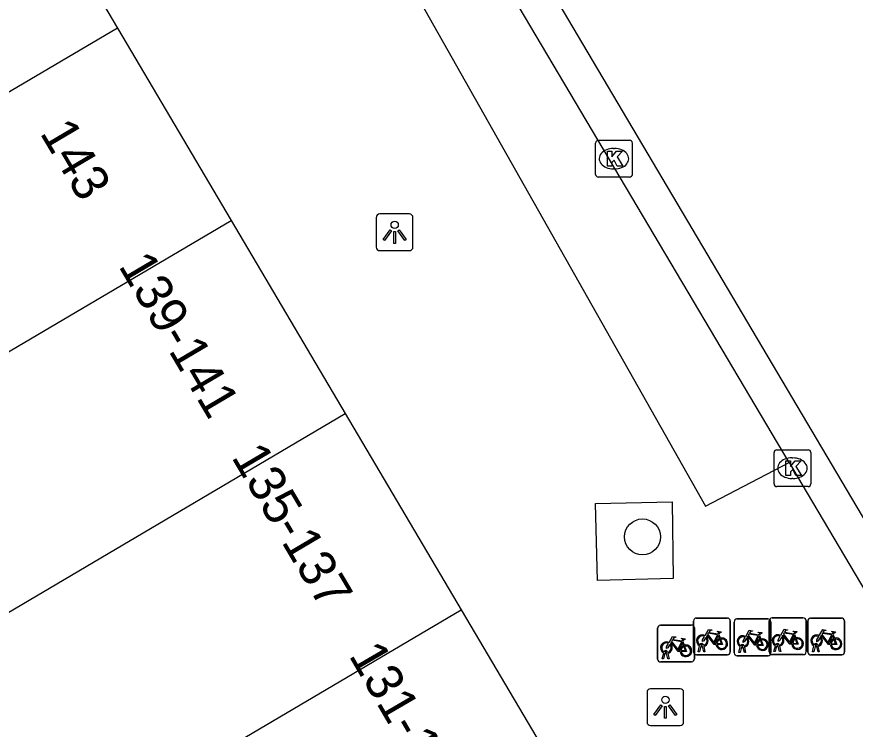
# Model space of a CAD drawing. Extents: x 160379 to 161131, y 383940 to 384849.
# Drawn here: x 161035.54 to 161058.35, y 384440.01 to 384459.39 of the extents above; entities that cross this region are included whole.
import ezdxf

# ---------------------------------------------------------------- set-up
doc = ezdxf.new("R2010")
doc.units = 0
for name, color, linetype in [('IMGEO_Boom', 7, 'Continuous'), ('IMGEO_Fietsenrek', 7, 'Continuous'), ('IMGEO_Fietspad_gesloten', 7, 'Continuous'), ('IMGEO_Fietspad_open', 7, 'Continuous'), ('IMGEO_Kolk', 7, 'Continuous'), ('IMGEO_Lichtpunt', 7, 'Continuous'), ('IMGEO_Pand', 7, 'Continuous'), ('IMGEO_Pand_nummerreeks', 7, 'Continuous'), ('IMGEO_Voetpad_open', 7, 'Continuous')]:
    doc.layers.add(name, color=color, linetype=linetype)

msp = doc.modelspace()

# ---------------------------------------------------------------- linework, layer by layer
at = {"layer": 'IMGEO_Boom'}
msp.add_circle((161052.564, 384445.239), 0.489, dxfattribs=at)
at = {"layer": 'IMGEO_Fietsenrek'}
for p, q in [((161054.027, 384443.033), (161054.868, 384443.033)), ((161054.868, 384443.033), (161054.027, 384443.033)), ((161055.133, 384443.009), (161055.974, 384443.009)), ((161055.974, 384443.009), (161055.133, 384443.009)), ((161056.089, 384443.037), (161056.93, 384443.037)), ((161056.93, 384443.037), (161056.089, 384443.037)), ((161057.136, 384443.031), (161057.977, 384443.031)), ((161057.977, 384443.031), (161057.136, 384443.031)), ((161053.05, 384442.842), (161053.891, 384442.842)), ((161053.891, 384442.842), (161053.05, 384442.842)), ((161053.952, 384442.108), (161053.952, 384442.949)), ((161053.952, 384442.949), (161053.952, 384442.108)), ((161054.952, 384442.958), (161054.952, 384442.117)), ((161054.952, 384442.117), (161054.952, 384442.958)), ((161055.058, 384442.084), (161055.058, 384442.925)), ((161055.058, 384442.925), (161055.058, 384442.084)), ((161056.014, 384442.112), (161056.014, 384442.953)), ((161056.014, 384442.953), (161056.014, 384442.112)), ((161056.058, 384442.934), (161056.058, 384442.093)), ((161056.058, 384442.093), (161056.058, 384442.934)), ((161057.014, 384442.962), (161057.014, 384442.121)), ((161057.014, 384442.121), (161057.014, 384442.962)), ((161057.061, 384442.106), (161057.061, 384442.947)), ((161057.061, 384442.947), (161057.061, 384442.106)), ((161058.061, 384442.956), (161058.061, 384442.115)), ((161058.061, 384442.115), (161058.061, 384442.956)), ((161052.975, 384441.917), (161052.975, 384442.758)), ((161052.975, 384442.758), (161052.975, 384441.917)), ((161053.975, 384442.767), (161053.975, 384441.926)), ((161053.975, 384441.926), (161053.975, 384442.767)), ((161054.639, 384442.582), (161054.675, 384442.487)), ((161055.745, 384442.558), (161055.781, 384442.463)), ((161056.701, 384442.586), (161056.737, 384442.491)), ((161057.748, 384442.58), (161057.784, 384442.485)), ((161053.662, 384442.391), (161053.698, 384442.296)), ((161053.213, 384442.098), (161053.212, 384442.102)), ((161053.244, 384442.109), (161053.245, 384442.102)), ((161054.079, 384442.117), (161054.118, 384442.277)), ((161054.113, 384442.117), (161054.079, 384442.117)), ((161054.148, 384442.265), (161054.113, 384442.117)), ((161054.19, 384442.289), (161054.189, 384442.293)), ((161054.231, 384442.117), (161054.197, 384442.259)), ((161054.221, 384442.3), (161054.222, 384442.293)), ((161054.229, 384442.263), (161054.264, 384442.117)), ((161054.264, 384442.117), (161054.231, 384442.117)), ((161055.185, 384442.093), (161055.224, 384442.253)), ((161055.219, 384442.093), (161055.185, 384442.093)), ((161055.254, 384442.241), (161055.219, 384442.093)), ((161055.296, 384442.265), (161055.295, 384442.269)), ((161055.337, 384442.093), (161055.303, 384442.235)), ((161055.327, 384442.276), (161055.328, 384442.269)), ((161055.335, 384442.239), (161055.37, 384442.093)), ((161055.37, 384442.093), (161055.337, 384442.093)), ((161056.141, 384442.121), (161056.18, 384442.281)), ((161056.175, 384442.121), (161056.141, 384442.121)), ((161056.21, 384442.269), (161056.175, 384442.121)), ((161056.252, 384442.293), (161056.251, 384442.297)), ((161056.293, 384442.121), (161056.259, 384442.263)), ((161056.283, 384442.304), (161056.284, 384442.297)), ((161056.291, 384442.267), (161056.326, 384442.121)), ((161056.326, 384442.121), (161056.293, 384442.121)), ((161057.188, 384442.115), (161057.227, 384442.275)), ((161057.222, 384442.115), (161057.188, 384442.115)), ((161057.257, 384442.263), (161057.222, 384442.115)), ((161057.299, 384442.287), (161057.298, 384442.291)), ((161057.34, 384442.115), (161057.306, 384442.257)), ((161057.33, 384442.298), (161057.331, 384442.291)), ((161057.338, 384442.261), (161057.373, 384442.115)), ((161057.373, 384442.115), (161057.34, 384442.115)), ((161053.102, 384441.926), (161053.141, 384442.086)), ((161053.136, 384441.926), (161053.102, 384441.926)), ((161053.171, 384442.074), (161053.136, 384441.926)), ((161053.254, 384441.926), (161053.22, 384442.068)), ((161053.252, 384442.072), (161053.287, 384441.926)), ((161053.287, 384441.926), (161053.254, 384441.926)), ((161054.877, 384442.033), (161054.036, 384442.033)), ((161054.036, 384442.033), (161054.877, 384442.033)), ((161055.983, 384442.009), (161055.142, 384442.009)), ((161055.142, 384442.009), (161055.983, 384442.009)), ((161056.939, 384442.037), (161056.098, 384442.037)), ((161056.098, 384442.037), (161056.939, 384442.037)), ((161057.986, 384442.031), (161057.145, 384442.031)), ((161057.145, 384442.031), (161057.986, 384442.031)), ((161053.9, 384441.842), (161053.059, 384441.842)), ((161053.059, 384441.842), (161053.9, 384441.842))]:
    msp.add_line(p, q, dxfattribs=at)
for points in [[(161054.265, 384442.559), (161054.36, 384442.723), (161054.446, 384442.709), (161054.448, 384442.7), (161054.392, 384442.689), (161054.365, 384442.644), (161054.621, 384442.603)], [(161054.561, 384442.315), (161054.511, 384442.315), (161054.32, 384442.566), (161054.301, 384442.534)], [(161054.608, 384442.578), (161054.351, 384442.619), (161054.334, 384442.59), (161054.501, 384442.37), (161054.608, 384442.578)], [(161054.656, 384442.48), (161054.626, 384442.557), (161054.517, 384442.339), (161054.56, 384442.339)], [(161054.621, 384442.603), (161054.646, 384442.652), (161054.64, 384442.656), (161054.617, 384442.66), (161054.605, 384442.667), (161054.604, 384442.67), (161054.606, 384442.675), (161054.701, 384442.66), (161054.703, 384442.65), (161054.693, 384442.637), (161054.681, 384442.631), (161054.667, 384442.637), (161054.639, 384442.582)], [(161055.371, 384442.535), (161055.466, 384442.699), (161055.552, 384442.685), (161055.554, 384442.676), (161055.498, 384442.665), (161055.471, 384442.62), (161055.727, 384442.579)], [(161055.714, 384442.554), (161055.457, 384442.595), (161055.44, 384442.566), (161055.607, 384442.346), (161055.714, 384442.554)], [(161055.727, 384442.579), (161055.752, 384442.628), (161055.746, 384442.632), (161055.723, 384442.636), (161055.711, 384442.643), (161055.71, 384442.646), (161055.712, 384442.651), (161055.807, 384442.636), (161055.809, 384442.626), (161055.799, 384442.613), (161055.787, 384442.607), (161055.773, 384442.613), (161055.745, 384442.558)], [(161056.327, 384442.563), (161056.422, 384442.727), (161056.508, 384442.713), (161056.51, 384442.704), (161056.454, 384442.693), (161056.427, 384442.648), (161056.683, 384442.607)], [(161056.623, 384442.319), (161056.573, 384442.319), (161056.382, 384442.57), (161056.363, 384442.538)], [(161056.67, 384442.582), (161056.413, 384442.623), (161056.396, 384442.594), (161056.563, 384442.374), (161056.67, 384442.582)], [(161056.718, 384442.484), (161056.688, 384442.561), (161056.579, 384442.343), (161056.622, 384442.343)], [(161056.683, 384442.607), (161056.708, 384442.656), (161056.702, 384442.66), (161056.679, 384442.664), (161056.667, 384442.671), (161056.666, 384442.674), (161056.668, 384442.679), (161056.763, 384442.664), (161056.765, 384442.654), (161056.755, 384442.641), (161056.743, 384442.635), (161056.729, 384442.641), (161056.701, 384442.586)], [(161057.374, 384442.557), (161057.469, 384442.721), (161057.555, 384442.707), (161057.557, 384442.698), (161057.501, 384442.687), (161057.474, 384442.642), (161057.73, 384442.601)], [(161057.67, 384442.313), (161057.62, 384442.313), (161057.429, 384442.564), (161057.41, 384442.532)], [(161057.717, 384442.576), (161057.46, 384442.617), (161057.443, 384442.588), (161057.61, 384442.368), (161057.717, 384442.576)], [(161057.765, 384442.478), (161057.735, 384442.555), (161057.626, 384442.337), (161057.669, 384442.337)], [(161057.73, 384442.601), (161057.755, 384442.65), (161057.749, 384442.654), (161057.726, 384442.658), (161057.714, 384442.665), (161057.713, 384442.668), (161057.715, 384442.673), (161057.81, 384442.658), (161057.812, 384442.648), (161057.802, 384442.635), (161057.79, 384442.629), (161057.776, 384442.635), (161057.748, 384442.58)], [(161053.309, 384442.316), (161053.257, 384442.226), (161053.217, 384442.201), (161053.218, 384442.248), (161053.273, 384442.342)], [(161053.288, 384442.368), (161053.383, 384442.532), (161053.469, 384442.518), (161053.471, 384442.509), (161053.415, 384442.498), (161053.388, 384442.453), (161053.644, 384442.412)], [(161053.584, 384442.124), (161053.534, 384442.124), (161053.343, 384442.375), (161053.324, 384442.343)], [(161053.631, 384442.387), (161053.374, 384442.428), (161053.357, 384442.399), (161053.524, 384442.179), (161053.631, 384442.387)], [(161053.679, 384442.289), (161053.649, 384442.366), (161053.54, 384442.148), (161053.583, 384442.148)], [(161053.644, 384442.412), (161053.669, 384442.461), (161053.663, 384442.465), (161053.64, 384442.469), (161053.628, 384442.476), (161053.627, 384442.479), (161053.629, 384442.484), (161053.724, 384442.469), (161053.726, 384442.459), (161053.716, 384442.446), (161053.704, 384442.44), (161053.69, 384442.446), (161053.662, 384442.391)], [(161054.286, 384442.507), (161054.234, 384442.417), (161054.194, 384442.392), (161054.195, 384442.439), (161054.25, 384442.533)], [(161054.59, 384442.339), (161054.71, 384442.338), (161054.666, 384442.452)], [(161054.686, 384442.459), (161054.741, 384442.314), (161054.591, 384442.314)], [(161055.392, 384442.483), (161055.34, 384442.393), (161055.3, 384442.368), (161055.301, 384442.415), (161055.356, 384442.509)], [(161055.667, 384442.291), (161055.617, 384442.291), (161055.426, 384442.542), (161055.407, 384442.51)], [(161055.762, 384442.456), (161055.732, 384442.533), (161055.623, 384442.315), (161055.666, 384442.315)], [(161055.696, 384442.315), (161055.816, 384442.314), (161055.772, 384442.428)], [(161055.792, 384442.435), (161055.847, 384442.29), (161055.697, 384442.29)], [(161056.348, 384442.511), (161056.296, 384442.421), (161056.256, 384442.396), (161056.257, 384442.443), (161056.312, 384442.537)], [(161056.652, 384442.343), (161056.772, 384442.342), (161056.728, 384442.456)], [(161056.748, 384442.463), (161056.803, 384442.318), (161056.653, 384442.318)], [(161057.395, 384442.505), (161057.343, 384442.415), (161057.303, 384442.39), (161057.304, 384442.437), (161057.359, 384442.531)], [(161057.699, 384442.337), (161057.819, 384442.336), (161057.775, 384442.45)], [(161057.795, 384442.457), (161057.85, 384442.312), (161057.7, 384442.312)], [(161053.613, 384442.148), (161053.733, 384442.147), (161053.689, 384442.261)], [(161053.709, 384442.268), (161053.764, 384442.123), (161053.614, 384442.123)]]:
    msp.add_lwpolyline(points, dxfattribs=at)
for centre, radius, start, end in [((161054.03, 384442.955), 0.0779, 92.4484, 184.2845), ((161054.03, 384442.955), 0.0779, 92.4484, 184.2845), ((161054.874, 384442.955), 0.0779, 2.4484, 94.2845), ((161054.874, 384442.955), 0.0779, 2.4484, 94.2845), ((161055.136, 384442.931), 0.0779, 92.4484, 184.2845), ((161055.136, 384442.931), 0.0779, 92.4484, 184.2845), ((161055.98, 384442.931), 0.0779, 2.4484, 94.2845), ((161055.98, 384442.931), 0.0779, 2.4484, 94.2845), ((161056.092, 384442.959), 0.0779, 92.4484, 184.2845), ((161056.092, 384442.959), 0.0779, 92.4484, 184.2845), ((161056.936, 384442.959), 0.0779, 2.4484, 94.2845), ((161056.936, 384442.959), 0.0779, 2.4484, 94.2845), ((161057.139, 384442.953), 0.0779, 92.4484, 184.2845), ((161057.139, 384442.953), 0.0779, 92.4484, 184.2845), ((161057.983, 384442.953), 0.0779, 2.4484, 94.2845), ((161057.983, 384442.953), 0.0779, 2.4484, 94.2845), ((161053.053, 384442.764), 0.0779, 92.4484, 184.2845), ((161053.053, 384442.764), 0.0779, 92.4484, 184.2845), ((161053.897, 384442.764), 0.0779, 2.4484, 94.2845), ((161053.897, 384442.764), 0.0779, 2.4484, 94.2845), ((161054.192, 384442.418), 0.159, 62.6766, 242.1369), ((161054.192, 384442.418), 0.129, 63.3192, 238.903), ((161055.298, 384442.394), 0.159, 62.6766, 242.1369), ((161056.254, 384442.422), 0.159, 62.6766, 242.1369), ((161056.254, 384442.422), 0.129, 63.3192, 238.903), ((161057.301, 384442.416), 0.159, 62.6766, 242.1369), ((161057.301, 384442.416), 0.129, 63.3192, 238.903), ((161053.215, 384442.227), 0.159, 62.6766, 242.1369), ((161053.215, 384442.227), 0.129, 63.3192, 238.903), ((161053.215, 384442.227), 0.159, 283.5766, 46.6042), ((161054.172, 384442.289), 0.0499, 12.8025, 158.6934), ((161054.192, 384442.418), 0.129, 283.6043, 43.4302), ((161054.192, 384442.418), 0.159, 283.5766, 46.6042), ((161054.719, 384442.334), 0.159, 113.3408, 178.3217), ((161054.719, 384442.334), 0.159, 187.0065, 105.7708), ((161054.719, 384442.334), 0.129, 113.923, 177.9556), ((161054.719, 384442.334), 0.129, 188.6715, 104.5883), ((161055.298, 384442.394), 0.129, 63.3192, 238.903), ((161055.298, 384442.394), 0.129, 283.6043, 43.4302), ((161055.298, 384442.394), 0.159, 283.5766, 46.6042), ((161055.825, 384442.31), 0.159, 113.3408, 178.3217), ((161055.825, 384442.31), 0.159, 187.0065, 105.7708), ((161055.825, 384442.31), 0.129, 113.923, 177.9556), ((161055.825, 384442.31), 0.129, 188.6715, 104.5883), ((161056.234, 384442.293), 0.0499, 12.8025, 158.6934), ((161056.254, 384442.422), 0.129, 283.6043, 43.4302), ((161056.254, 384442.422), 0.159, 283.5766, 46.6042), ((161056.781, 384442.338), 0.159, 113.3408, 178.3217), ((161056.781, 384442.338), 0.159, 187.0065, 105.7708), ((161056.781, 384442.338), 0.129, 113.923, 177.9556), ((161056.781, 384442.338), 0.129, 188.6715, 104.5883), ((161057.281, 384442.287), 0.0499, 12.8025, 158.6934), ((161057.301, 384442.416), 0.129, 283.6043, 43.4302), ((161057.301, 384442.416), 0.159, 283.5766, 46.6042), ((161057.828, 384442.332), 0.159, 113.3408, 178.3217), ((161057.828, 384442.332), 0.159, 187.0065, 105.7708), ((161057.828, 384442.332), 0.129, 113.923, 177.9556), ((161057.828, 384442.332), 0.129, 188.6715, 104.5883), ((161053.195, 384442.098), 0.0499, 12.8025, 158.6934), ((161053.195, 384442.098), 0.0174, 12.8025, 163.4502), ((161053.215, 384442.227), 0.129, 253.415, 269.0204), ((161053.215, 384442.227), 0.129, 283.6043, 43.4302), ((161053.742, 384442.143), 0.159, 113.3408, 178.3217), ((161053.742, 384442.143), 0.159, 187.0065, 105.7708), ((161053.742, 384442.143), 0.129, 113.923, 177.9556), ((161053.742, 384442.143), 0.129, 188.6715, 104.5883), ((161054.03, 384442.111), 0.0779, 182.4484, 274.2845), ((161054.03, 384442.111), 0.0779, 182.4484, 274.2845), ((161054.192, 384442.418), 0.159, 253.9967, 271.7867), ((161054.172, 384442.289), 0.0174, 12.8025, 163.4502), ((161054.192, 384442.418), 0.129, 253.415, 269.0204), ((161054.874, 384442.111), 0.0779, 272.4484, 4.2845), ((161054.874, 384442.111), 0.0779, 272.4484, 4.2845), ((161055.278, 384442.265), 0.0499, 12.8025, 158.6934), ((161055.298, 384442.394), 0.159, 253.9967, 271.7867), ((161055.278, 384442.265), 0.0174, 12.8025, 163.4502), ((161055.298, 384442.394), 0.129, 253.415, 269.0204), ((161055.98, 384442.087), 0.0779, 272.4484, 4.2845), ((161055.98, 384442.087), 0.0779, 272.4484, 4.2845), ((161056.092, 384442.115), 0.0779, 182.4484, 274.2845), ((161056.092, 384442.115), 0.0779, 182.4484, 274.2845), ((161056.254, 384442.422), 0.159, 253.9967, 271.7867), ((161056.234, 384442.293), 0.0174, 12.8025, 163.4502), ((161056.254, 384442.422), 0.129, 253.415, 269.0204), ((161056.936, 384442.115), 0.0779, 272.4484, 4.2845), ((161056.936, 384442.115), 0.0779, 272.4484, 4.2845), ((161057.139, 384442.109), 0.0779, 182.4484, 274.2845), ((161057.139, 384442.109), 0.0779, 182.4484, 274.2845), ((161057.301, 384442.416), 0.159, 253.9967, 271.7867), ((161057.281, 384442.287), 0.0174, 12.8025, 163.4502), ((161057.301, 384442.416), 0.129, 253.415, 269.0204), ((161057.983, 384442.109), 0.0779, 272.4484, 4.2845), ((161057.983, 384442.109), 0.0779, 272.4484, 4.2845), ((161053.053, 384441.92), 0.0779, 182.4484, 274.2845), ((161053.053, 384441.92), 0.0779, 182.4484, 274.2845), ((161053.215, 384442.227), 0.159, 253.9967, 271.7867), ((161053.897, 384441.92), 0.0779, 272.4484, 4.2845), ((161053.897, 384441.92), 0.0779, 272.4484, 4.2845), ((161055.136, 384442.087), 0.0779, 182.4484, 274.2845), ((161055.136, 384442.087), 0.0779, 182.4484, 274.2845)]:
    msp.add_arc(centre, radius, start, end, dxfattribs=at)
at = {"layer": 'IMGEO_Fietspad_gesloten'}
msp.add_lwpolyline([(161035.767, 384484.262), (161059.475, 384444.228)], dxfattribs=at)
at = {"layer": 'IMGEO_Fietspad_open'}
for points in [[(161056.553, 384447.261), (161047.068, 384463.264), (161045.415, 384466.054), (161044.226, 384468.061)], [(161056.553, 384447.261), (161056.903, 384446.671), (161058.642, 384443.737)]]:
    msp.add_lwpolyline(points, dxfattribs=at)
at = {"layer": 'IMGEO_Kolk'}
for p, q in [((161051.361, 384456.028), (161052.213, 384456.028)), ((161051.286, 384455.102), (161051.286, 384455.954)), ((161051.774, 384455.808), (161051.799, 384455.808)), ((161052.287, 384455.954), (161052.287, 384455.102)), ((161051.797, 384455.248), (161051.772, 384455.248)), ((161052.213, 384455.028), (161051.361, 384455.028)), ((161056.217, 384447.609), (161057.069, 384447.609)), ((161056.142, 384446.683), (161056.142, 384447.535)), ((161056.63, 384447.389), (161056.655, 384447.389)), ((161057.143, 384447.535), (161057.143, 384446.683)), ((161056.653, 384446.829), (161056.628, 384446.829)), ((161057.069, 384446.609), (161056.217, 384446.609))]:
    msp.add_line(p, q, dxfattribs=at)
for points in [[(161051.361, 384456.028), (161052.213, 384456.028)], [(161051.286, 384455.102), (161051.286, 384455.954)], [(161052.287, 384455.954), (161052.287, 384455.102)], [(161051.607, 384455.728), (161051.73, 384455.728), (161051.73, 384455.577), (161051.86, 384455.728), (161052.024, 384455.728), (161051.878, 384455.577), (161052.031, 384455.328), (161051.879, 384455.328), (161051.794, 384455.492), (161051.73, 384455.425), (161051.73, 384455.328), (161051.607, 384455.328), (161051.607, 384455.728)], [(161052.213, 384455.028), (161051.361, 384455.028)], [(161056.217, 384447.609), (161057.069, 384447.609)], [(161056.142, 384446.683), (161056.142, 384447.535)], [(161057.143, 384447.535), (161057.143, 384446.683)], [(161056.463, 384447.309), (161056.586, 384447.309), (161056.586, 384447.158), (161056.716, 384447.309), (161056.88, 384447.309), (161056.734, 384447.158), (161056.887, 384446.909), (161056.735, 384446.909), (161056.65, 384447.073), (161056.586, 384447.006), (161056.586, 384446.909), (161056.463, 384446.909), (161056.463, 384447.309)], [(161057.069, 384446.609), (161056.217, 384446.609)]]:
    msp.add_lwpolyline(points, dxfattribs=at)
for centre, start, end in [((161051.363, 384455.952), 91.552, 178.448), ((161051.363, 384455.952), 91.552, 178.448), ((161052.211, 384455.952), 1.552, 88.448), ((161052.211, 384455.952), 1.552, 88.448), ((161051.363, 384455.104), 181.552, 268.448), ((161051.363, 384455.104), 181.552, 268.448), ((161052.211, 384455.104), 271.552, 358.448), ((161052.211, 384455.104), 271.552, 358.448), ((161056.219, 384447.533), 91.552, 178.448), ((161056.219, 384447.533), 91.552, 178.448), ((161057.067, 384447.533), 1.552, 88.448), ((161057.067, 384447.533), 1.552, 88.448), ((161056.219, 384446.685), 181.552, 268.448), ((161056.219, 384446.685), 181.552, 268.448), ((161057.067, 384446.685), 271.552, 358.448), ((161057.067, 384446.685), 271.552, 358.448)]:
    msp.add_arc(centre, 0.0765, start, end, dxfattribs=at)
for centre, major_axis, ratio, start_param, end_param in [((161051.773, 384455.528), (-0.387, 0.002), 0.722429, 4.712389, 7.853982), ((161051.798, 384455.528), (-0.39, 0.002), 0.717154, 1.570796, 4.712389), ((161056.629, 384447.109), (-0.387, 0.002), 0.722429, 4.712389, 7.853982), ((161056.654, 384447.109), (-0.39, 0.002), 0.717154, 1.570796, 4.712389)]:
    msp.add_ellipse(centre, major_axis=major_axis, ratio=ratio, start_param=start_param, end_param=end_param, dxfattribs=at)
at = {"layer": 'IMGEO_Lichtpunt'}
for p, q in [((161046.224, 384454.024), (161045.416, 384454.024)), ((161046.224, 384454.024), (161045.416, 384454.024)), ((161045.322, 384453.929), (161045.322, 384453.122)), ((161045.322, 384453.929), (161045.322, 384453.122)), ((161046.318, 384453.122), (161046.318, 384453.929)), ((161046.318, 384453.122), (161046.318, 384453.929)), ((161045.416, 384453.028), (161046.224, 384453.028)), ((161045.416, 384453.028), (161046.224, 384453.028)), ((161052.687, 384441.012), (161052.687, 384440.205)), ((161052.687, 384441.012), (161052.687, 384440.205)), ((161053.589, 384441.107), (161052.781, 384441.107)), ((161053.589, 384441.107), (161052.781, 384441.107)), ((161053.683, 384440.205), (161053.683, 384441.012)), ((161053.683, 384440.205), (161053.683, 384441.012)), ((161052.781, 384440.111), (161053.589, 384440.111)), ((161052.781, 384440.111), (161053.589, 384440.111))]:
    msp.add_line(p, q, dxfattribs=at)
for points in [[(161045.696, 384453.593), (161045.735, 384453.565), (161045.547, 384453.303), (161045.509, 384453.33), (161045.696, 384453.593)], [(161045.798, 384453.545), (161045.845, 384453.545), (161045.845, 384453.223), (161045.798, 384453.223), (161045.798, 384453.545)], [(161045.908, 384453.565), (161045.946, 384453.592), (161046.133, 384453.33), (161046.094, 384453.302), (161045.908, 384453.565)], [(161053.061, 384440.676), (161053.1, 384440.648), (161052.912, 384440.386), (161052.874, 384440.413), (161053.061, 384440.676)], [(161053.163, 384440.628), (161053.21, 384440.628), (161053.21, 384440.306), (161053.163, 384440.306), (161053.163, 384440.628)], [(161053.273, 384440.648), (161053.311, 384440.675), (161053.498, 384440.413), (161053.459, 384440.385), (161053.273, 384440.648)]]:
    msp.add_lwpolyline(points, dxfattribs=at)
for centre in [(161045.821, 384453.727), (161053.186, 384440.81)]:
    msp.add_circle(centre, 0.0994, dxfattribs=at)
for centre, start, end in [((161045.416, 384453.929), 90, 180), ((161045.416, 384453.929), 90, 180), ((161046.224, 384453.929), 0, 90), ((161046.224, 384453.929), 0, 90), ((161045.416, 384453.122), 180, 270), ((161045.416, 384453.122), 180, 270), ((161046.224, 384453.122), 270, 0), ((161046.224, 384453.122), 270, 360), ((161052.781, 384441.012), 90, 180), ((161052.781, 384441.012), 90, 180), ((161053.589, 384441.012), 0, 90), ((161053.589, 384441.012), 0, 90), ((161052.781, 384440.205), 180, 270), ((161052.781, 384440.205), 180, 270), ((161053.589, 384440.205), 270, 0), ((161053.589, 384440.205), 270, 360)]:
    msp.add_arc(centre, 0.0946, start, end, dxfattribs=at)
at = {"layer": 'IMGEO_Pand'}
for points in [[(161035.213, 384464.264), (161038.277, 384459.081)], [(161038.277, 384459.081), (161024.16, 384450.76)], [(161038.277, 384459.081), (161041.371, 384453.848)], [(161027.259, 384445.528), (161041.371, 384453.848)], [(161041.371, 384453.848), (161044.477, 384448.594)], [(161030.369, 384440.277), (161044.477, 384448.594)], [(161044.477, 384448.594), (161047.632, 384443.257)], [(161033.528, 384434.943), (161047.632, 384443.257)], [(161047.632, 384443.257), (161050.517, 384438.378), (161050.66, 384438.06)]]:
    msp.add_lwpolyline(points, dxfattribs=at)
at = {"layer": 'IMGEO_Voetpad_open'}
for points in [[(161044.226, 384468.061), (161042.455, 384466.99), (161054.28, 384446.072), (161056.553, 384447.261)], [(161053.372, 384446.19), (161053.396, 384444.107), (161051.338, 384444.058), (161051.281, 384446.149), (161053.372, 384446.19)]]:
    msp.add_lwpolyline(points, dxfattribs=at)

# ---------------------------------------------------------------- texts
at = {"layer": 'IMGEO_Pand_nummerreeks'}
for s, rotation, p in [('143', 300.5918, (161036.153, 384456.23)), ('139-141', 300.5918, (161038.291, 384452.613)), ('135-137', 300.5918, (161041.365, 384447.413)), ('131-133', 300.2228, (161044.558, 384442.018))]:
    msp.add_text(s, height=1, rotation=rotation, dxfattribs=at).set_placement(p)

doc.saveas('drawing.dxf')
